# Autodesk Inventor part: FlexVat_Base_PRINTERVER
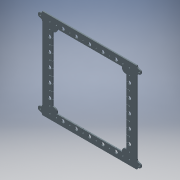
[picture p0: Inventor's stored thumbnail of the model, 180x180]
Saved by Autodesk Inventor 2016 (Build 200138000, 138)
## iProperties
Created: 2015-11
Part Number: FlexVat_Base_PRINTERVER
Material: Generic
Document SubType Name: Modeling
Designer: John
Density: 1 g/cm^3
Appearance: Default
Author: John
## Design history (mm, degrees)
feature "Base1"
body "Solid1"
